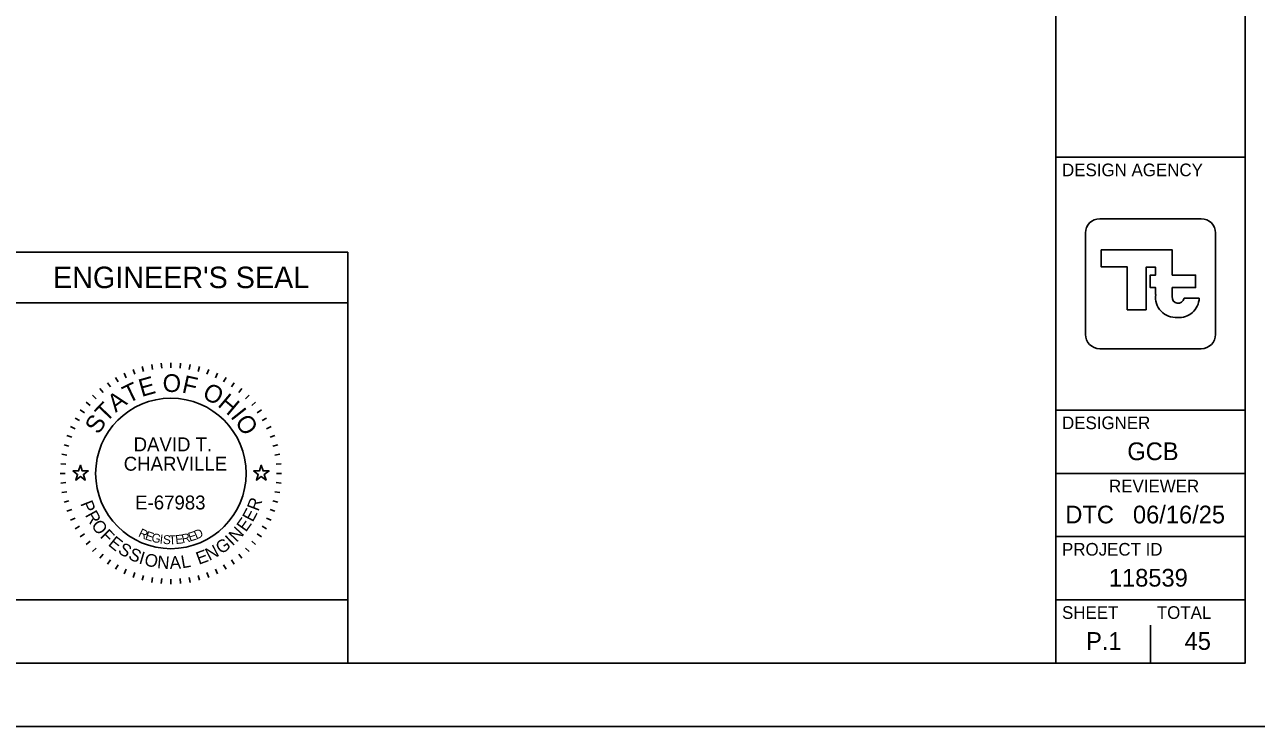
# Model space of a CAD drawing. Extents: x -8.3 to 42.1, y 0 to 22.
# Drawn here: x 23.84 to 33.59, y 0 to 5.55 of the extents above; entities that cross this region are included whole.
import ezdxf

# ---------------------------------------------------------------- set-up
doc = ezdxf.new("R2010")
doc.units = 0
for name, color, linetype in [('Default', 7, 'Continuous'), ('SH_Border', 7, 'Continuous'), ('SH_Cut_Line', 7, 'Continuous'), ('SH_Data', 7, 'Continuous')]:
    doc.layers.add(name, color=color, linetype=linetype)

msp = doc.modelspace()

# ---------------------------------------------------------------- linework, layer by layer
at = {"layer": 'Default'}
for points in [[(24.2236, 2.02), (24.2705, 2.02), (24.285, 2.0645), (24.2995, 2.02), (24.3464, 2.02), (24.3085, 1.9924), (24.323, 1.9478), (24.285, 1.9754), (24.247, 1.9478), (24.2615, 1.9924)], [(25.6536, 2.02), (25.7005, 2.02), (25.715, 2.0645), (25.7295, 2.02), (25.7764, 2.02), (25.7385, 1.9924), (25.753, 1.9478), (25.715, 1.9754), (25.677, 1.9478), (25.6915, 1.9924)]]:
    msp.add_lwpolyline(points, close=True, dxfattribs=at)
at = {"layer": 'SH_Border'}
for p, q in [((32, 0.5), (32, 21.5)), ((32, 4.5), (33.5, 4.5)), ((32, 2.5), (33.5, 2.5)), ((32, 2), (33.5, 2)), ((32, 1.5), (33.5, 1.5)), ((32, 1), (33.5, 1))]:
    msp.add_line(p, q, dxfattribs=at)
msp.add_lwpolyline([(1.5, 21.5), (33.5, 21.5), (33.5, 0.5), (1.5, 0.5)], close=True, dxfattribs=at)
at = {"layer": 'SH_Cut_Line'}
msp.add_lwpolyline([(0, 0), (34, 0), (34, 22), (0, 22)], close=True, dxfattribs=at)
at = {"layer": 'SH_Data'}
for p, q in [((23.6, 3.75), (26.4, 3.75)), ((26.4, 3.75), (26.4, 0.5)), ((32.75, 3.5), (32.75, 3.5)), ((32.7911, 3.4149), (32.7911, 3.4149)), ((23.6, 3.35), (26.4, 3.35)), ((33.1355, 3.3849), (33.0152, 3.3849)), ((24.7735, 2.8452), (24.7839, 2.8065)), ((24.8481, 2.8617), (24.855, 2.8223)), ((24.9237, 2.8717), (24.9272, 2.8318)), ((25, 2.875), (25, 2.835)), ((25.0763, 2.8717), (25.0728, 2.8318)), ((25.1519, 2.8617), (25.145, 2.8223)), ((25.2265, 2.8452), (25.2161, 2.8065)), ((24.5625, 2.7578), (24.5825, 2.7231)), ((24.6302, 2.793), (24.6471, 2.7568)), ((24.7007, 2.8222), (24.7144, 2.7846)), ((25.2993, 2.8222), (25.2856, 2.7846)), ((25.3698, 2.793), (25.3529, 2.7568)), ((25.4375, 2.7578), (25.4175, 2.7231)), ((24.4376, 2.6703), (24.4633, 2.6396)), ((24.4981, 2.7168), (24.5211, 2.684)), ((25.5019, 2.7168), (25.4789, 2.684)), ((25.5624, 2.6703), (25.5367, 2.6396)), ((24.3297, 2.5624), (24.3604, 2.5367)), ((24.3813, 2.6187), (24.4096, 2.5904)), ((25.6187, 2.6187), (25.5904, 2.5904)), ((25.6703, 2.5624), (25.6396, 2.5367)), ((24.2422, 2.4375), (24.2769, 2.4175)), ((24.2832, 2.5019), (24.316, 2.4789)), ((25.7168, 2.5019), (25.684, 2.4789)), ((25.7578, 2.4375), (25.7231, 2.4175)), ((24.207, 2.3698), (24.2432, 2.3529)), ((25.793, 2.3698), (25.7568, 2.3529)), ((24.1778, 2.2993), (24.2154, 2.2856)), ((25.8222, 2.2993), (25.7846, 2.2856)), ((24.1383, 2.1519), (24.1777, 2.145)), ((24.1548, 2.2265), (24.1935, 2.2161)), ((25.8452, 2.2265), (25.8065, 2.2161)), ((25.8617, 2.1519), (25.8223, 2.145)), ((24.1283, 2.0763), (24.1682, 2.0728)), ((25.8717, 2.0763), (25.8318, 2.0728)), ((24.125, 2), (24.165, 2)), ((25.875, 2), (25.835, 2)), ((24.1283, 1.9237), (24.1682, 1.9272)), ((24.1383, 1.8481), (24.1777, 1.855)), ((25.8617, 1.8481), (25.8223, 1.855)), ((25.8717, 1.9237), (25.8318, 1.9272)), ((24.1548, 1.7735), (24.1935, 1.7839)), ((25.8452, 1.7735), (25.8065, 1.7839)), ((24.1778, 1.7007), (24.2154, 1.7144)), ((25.8222, 1.7007), (25.7846, 1.7144)), ((24.207, 1.6302), (24.2432, 1.6471)), ((24.2422, 1.5625), (24.2769, 1.5825)), ((25.7578, 1.5625), (25.7231, 1.5825)), ((25.793, 1.6302), (25.7568, 1.6471)), ((24.2832, 1.4981), (24.316, 1.5211)), ((24.3297, 1.4376), (24.3604, 1.4633)), ((25.6703, 1.4376), (25.6396, 1.4633)), ((25.7168, 1.4981), (25.684, 1.5211)), ((24.3813, 1.3813), (24.4096, 1.4096)), ((25.6187, 1.3813), (25.5904, 1.4096)), ((24.4376, 1.3297), (24.4633, 1.3604)), ((24.4981, 1.2832), (24.5211, 1.316)), ((24.5625, 1.2422), (24.5825, 1.2769)), ((25.4375, 1.2422), (25.4175, 1.2769)), ((25.5019, 1.2832), (25.4789, 1.316)), ((25.5624, 1.3297), (25.5367, 1.3604)), ((24.6302, 1.207), (24.6471, 1.2432)), ((24.7007, 1.1778), (24.7144, 1.2154)), ((24.7735, 1.1548), (24.7839, 1.1935)), ((24.8481, 1.1383), (24.855, 1.1777)), ((25.1519, 1.1383), (25.145, 1.1777)), ((25.2265, 1.1548), (25.2161, 1.1935)), ((25.2993, 1.1778), (25.2856, 1.2154)), ((25.3698, 1.207), (25.3529, 1.2432)), ((24.9237, 1.1283), (24.9272, 1.1682)), ((25, 1.125), (25, 1.165)), ((25.0763, 1.1283), (25.0728, 1.1682)), ((32.75, 0.5), (32.75, 0.8)), ((32.375, 0.675), (32.375, 0.675)), ((23.6, 0.5), (26.4, 0.5))]:
    msp.add_line(p, q, dxfattribs=at)
for points in [[(32.3483, 4.0138), (33.1517, 4.0138)], [(32.2356, 3.0989), (32.2356, 3.9011)], [(33.2644, 3.9011), (33.2644, 3.0989)], [(32.9216, 3.3991), (32.9216, 3.4701), (33.1068, 3.4701), (33.1068, 3.5679), (32.9216, 3.5679), (32.9216, 3.7677), (32.3609, 3.7677), (32.3609, 3.6324), (32.5658, 3.6324), (32.5658, 3.2942), (32.7146, 3.2942), (32.7146, 3.6303), (32.7895, 3.6303), (32.7895, 3.5679), (32.7479, 3.5679), (32.7479, 3.4701), (32.7895, 3.4701), (32.7895, 3.4149), (32.7911, 3.4149)], [(33.1517, 2.9862), (32.3483, 2.9862)]]:
    msp.add_lwpolyline(points, dxfattribs=at)
msp.add_lwpolyline([(23.6, 0.5), (23.6, 1), (26.4, 1), (26.4, 0.5)], close=True, dxfattribs=at)
msp.add_circle((25, 2), 0.595, dxfattribs=at)
for centre, radius, start, end in [((32.3483, 3.9011), 0.1127, 90, 180), ((33.1517, 3.9011), 0.1127, 360, 90), ((32.9492, 3.3924), 0.1597, 171.88555, 274.83226), ((32.9685, 3.3924), 0.0473, 171.88555, 350.92431), ((32.976, 3.3924), 0.1597, 265.16774, 357.32013), ((32.3483, 3.0989), 0.1127, 180, 270), ((33.1517, 3.0989), 0.1127, 270, 360)]:
    msp.add_arc(centre, radius, start, end, dxfattribs=at)

# ---------------------------------------------------------------- texts
for s, height, p in [('DESIGN AGENCY', 0.1, (32.05, 4.35)), ("ENGINEER'S SEAL", 0.17, (24.0676, 3.465)), ('DESIGNER', 0.1, (32.05, 2.35)), ('DAVID T.', 0.11, (24.7054, 2.1749)), ('GCB', 0.14, (32.5664, 2.105)), ('CHARVILLE', 0.11, (24.6271, 2.0216)), ('REVIEWER', 0.1, (32.4218, 1.85)), ('E-67983', 0.11, (24.7177, 1.7151)), ('DTC', 0.14, (32.0761, 1.605)), ('06/16/25', 0.14, (32.611, 1.605)), ('PROJECT ID', 0.1, (32.05, 1.35)), ('118539', 0.14, (32.4204, 1.105)), ('SHEET', 0.1, (32.05, 0.85)), ('TOTAL', 0.1, (32.8, 0.85)), ('P.1', 0.14, (32.2403, 0.605)), ('45', 0.14, (33.0197, 0.605))]:
    msp.add_text(s, height=height, dxfattribs=at).set_placement(p)
for s, height, rotation, p in [('E', 0.14, 15.75706, (24.7684, 2.6038)), ('O', 0.14, 359.78119, (24.9347, 2.6443)), ('F', 0.14, 347.43619, (25.0811, 2.6417)), ('A', 0.14, 36.47472, (24.5634, 2.4781)), ('T', 0.14, 25.71674, (24.6616, 2.5518)), ('O', 0.14, 332.25863, (25.2398, 2.6015)), ('H', 0.14, 319.91363, (25.3632, 2.5361)), ('T', 0.14, 46.4344, (24.4883, 2.3964)), ('S', 0.14, 57.19238, (24.4281, 2.3014)), ('I', 0.14, 308.36695, (25.4665, 2.4483)), ('O', 0.14, 303.14906, (25.5021, 2.4089)), ('P', 0.1, 291.49398, (24.2823, 1.7621)), ('R', 0.1, 69.23216, (25.6919, 1.6954)), ('R', 0.1, 298.73106, (24.319, 1.6717)), ('E', 0.1, 61.99508, (25.6476, 1.6098)), ('O', 0.1, 306.46664, (24.3655, 1.5883)), ('F', 0.1, 314.7068, (24.4343, 1.4983)), ('R', 0.07, 334.48695, (24.7375, 1.5051)), ('D', 0.07, 23.30524, (25.201, 1.477)), ('N', 0.1, 47.02243, (25.5202, 1.4508)), ('E', 0.1, 54.75801, (25.5933, 1.5314)), ('E', 0.1, 321.43929, (24.4978, 1.4348)), ('E', 0.07, 341.03996, (24.7906, 1.4801)), ('G', 0.07, 347.47515, (24.8414, 1.4618)), ('I', 0.07, 353.78581, (24.9091, 1.4468)), ('S', 0.07, 356.89262, (24.9358, 1.4429)), ('T', 0.07, 3.00609, (24.9857, 1.4387)), ('E', 0.07, 6.01169, (25.0389, 1.4412)), ('R', 0.07, 11.91844, (25.0925, 1.4474)), ('E', 0.07, 17.68363, (25.1498, 1.4602)), ('G', 0.1, 35.04687, (25.3981, 1.357)), ('I', 0.1, 43.28703, (25.4868, 1.4214)), ('S', 0.1, 328.67637, (24.5743, 1.3752)), ('S', 0.1, 335.91345, (24.6564, 1.3266)), ('I', 0.1, 343.15053, (24.7406, 1.2897)), ('O', 0.1, 346.88592, (24.7839, 1.2751)), ('E', 0.1, 20.07421, (25.2212, 1.277)), ('N', 0.1, 27.31129, (25.3045, 1.3075)), ('N', 0.1, 355.12608, (24.8888, 1.2517)), ('A', 0.1, 2.86166, (24.9923, 1.2437)), ('L', 0.1, 10.09874, (25.0894, 1.249))]:
    msp.add_text(s, height=height, rotation=rotation, dxfattribs=at).set_placement(p)

doc.saveas('drawing.dxf')
